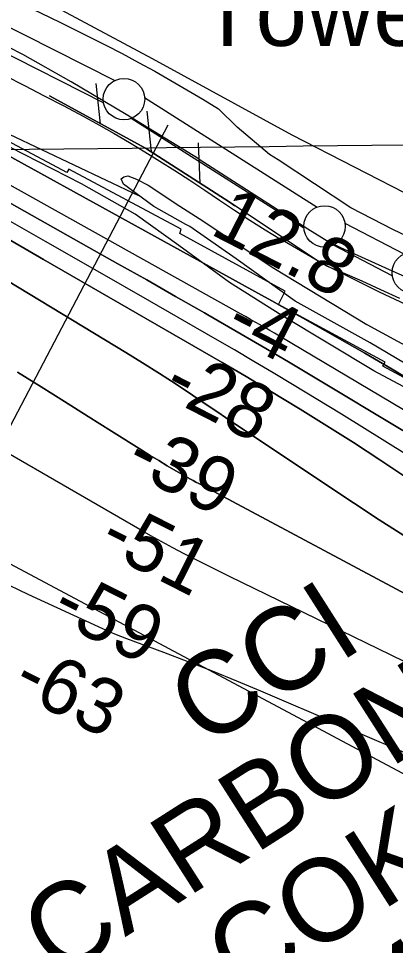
# Model space of a CAD drawing. Extents: x 3704301 to 3742427, y 506229 to 532009.
# Drawn here: x 3708455 to 3708909, y 522807 to 523925 of the extents above; entities that cross this region are included whole.
import ezdxf

# ---------------------------------------------------------------- set-up
doc = ezdxf.new("R2010")
doc.units = 0
for name, color, linetype in [('V-CHAN-NAID', 7, 'Continuous'), ('V-DOMW-IDEN', 7, 'Continuous'), ('V-FLOD-BASE', 7, 'Continuous'), ('V-GRID-MAJR', 7, 'Continuous'), ('V-LEVE-TOET', 7, 'Continuous'), ('V-RIVR-EDGE', 7, 'Continuous'), ('V-RIVR-RANG', 7, 'Continuous'), ('V-RRAP-FSHR', 7, 'Continuous'), ('V-RRAP-RVMT', 7, 'Continuous'), ('V-SITE-OTLN', 7, 'Continuous'), ('V-SITE-VEGE', 7, 'Continuous'), ('V-SURV-LINE', 7, 'Continuous'), ('V-TOPO-DPTH', 7, 'Continuous'), ('V-TOPO-MAJR', 7, 'Continuous'), ('V-TOPO-MINR', 7, 'Continuous'), ('V-TOPO-WATR', 7, 'Continuous')]:
    doc.layers.add(name, color=color, linetype=linetype)

msp = doc.modelspace()

# ---------------------------------------------------------------- linework, layer by layer
at = {"layer": 'V-FLOD-BASE'}
for points in [[(3708672.815, 523755.58), (3708584.865, 523809.742), (3708518.5160000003, 523849.131), (3708460.504, 523881.911), (3708425.5694070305, 523899.65617279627)], [(3708672.815, 523755.58), (3708745.3340000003, 523708.9), (3708803.6350000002, 523671.651), (3708829.228, 523656.09500000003), (3708842.971, 523649.02900000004), (3708909.772, 523618.89900000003), (3708991.733, 523582.653), (3709081.7430000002, 523545.007), (3709117.2800000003, 523527.583), (3709134.8170000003, 523516.739), (3709176.5300000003, 523488.916), (3709185.0640000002, 523482.31200000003), (3709195.026, 523472.868), (3709199.7770000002, 523465.30700000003), (3709202.157, 523459.634), (3709201.235, 523449.22000000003), (3709198.421, 523437.856)]]:
    msp.add_lwpolyline(points, dxfattribs=at)
at = {"layer": 'V-GRID-MAJR'}
msp.add_spline([(3708427.129, 523767.243), (3713705.816, 523829.819), (3718984.494, 523893.163), (3724263.162, 523957.275), (3729541.821, 524022.155), (3734820.471, 524087.803), (3740099.111, 524154.218), (3740099.112, 524154.218)], degree=3, dxfattribs=at)
at = {"layer": 'V-LEVE-TOET'}
for points in [[(3708424.8581686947, 523960.0234815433), (3708449.116, 523948.271), (3708504.8030000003, 523920.989), (3708560.3710000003, 523893.47000000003), (3708580.143, 523883.126), (3708599.795, 523872.554), (3708619.325, 523861.761), (3708638.73, 523850.743), (3708658.007, 523839.503), (3708677.156, 523828.047), (3708696.1720000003, 523816.371)], [(3708426.002542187, 523862.89324485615), (3708438.497, 523856.569), (3708462.225, 523844.46400000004), (3708485.91, 523832.282), (3708509.552, 523820.02900000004), (3708533.153, 523807.7), (3708551.88, 523797.282), (3708570.486, 523786.646), (3708588.967, 523775.798), (3708607.324, 523764.737), (3708625.551, 523753.467), (3708643.645, 523741.98600000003), (3708661.608, 523730.29600000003), (3708679.434, 523718.401), (3708697.419, 523706.129), (3708715.5500000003, 523694.069), (3708733.818, 523682.221), (3708752.2260000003, 523670.586), (3708770.764, 523659.169)], [(3708757.727, 523761.462), (3708718.62, 523794.482), (3708696.1720000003, 523816.371)], [(3709197.717, 523535.347), (3709110.538, 523576.313), (3709007.728, 523622.446), (3708906.809, 523670.478), (3708855.633, 523696.858), (3708767.94, 523754.859), (3708757.727, 523761.462)], [(3708914.489, 523587.677), (3708891.795, 523598.147), (3708869.001, 523608.397), (3708846.1040000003, 523618.424), (3708826.488, 523626.788), (3708770.764, 523659.169)]]:
    msp.add_lwpolyline(points, dxfattribs=at)
at = {"layer": 'V-RIVR-EDGE'}
msp.add_lwpolyline([(3708960.1091392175, 523459.0963712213), (3708883.3687410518, 523500.1083391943), (3708772.4737643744, 523567.01880682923), (3708709.537825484, 523606.79598707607), (3708648.4147308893, 523651.37129774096), (3708595.679829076, 523689.32227385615), (3708530.9354991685, 523726.1022925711), (3708444.59735574, 523770.13962617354)], dxfattribs=at)
at = {"layer": 'V-RIVR-RANG'}
msp.add_line((3708635.0474999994, 523796.8230000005), (3708431.3601537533, 523408.158769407), dxfattribs=at)
at = {"layer": 'V-RRAP-FSHR'}
for p, q in [((3708554.023, 523798.553), (3708548.645, 523847.087)), ((3708615.437, 523764.962), (3708610.059, 523813.496)), ((3708673.975, 523726.537), (3708672.1, 523775.331))]:
    msp.add_line(p, q, dxfattribs=at)
for points in [[(3709177.028, 523451.364), (3709162.396, 523470.18700000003), (3709116.876, 523494.681), (3708985.221, 523550.533), (3708890.261, 523595.17100000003), (3708817.731, 523631.577), (3708708.875, 523704.04600000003), (3708608.241, 523768.898), (3708492.609, 523832.14400000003)], [(3708492.609, 523832.14400000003), (3708608.241, 523768.898), (3708691.882, 523714.99700000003)], [(3708492.609, 523832.14400000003), (3708608.241, 523768.898), (3708708.875, 523704.04600000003), (3708715.738, 523699.477)], [(3708426.801692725, 523795.0642698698), (3708443.9034086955, 523785.80477121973), (3708599.73163284, 523711.96617915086)]]:
    msp.add_lwpolyline(points, dxfattribs=at)
at = {"layer": 'V-RRAP-RVMT'}
for p, q in [((3708513.4930000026, 523739.83000000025), (3708426.9114247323, 523785.75061843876)), ((3708515.6950000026, 523743.77500000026), (3708513.4930000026, 523739.83000000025)), ((3708651.121000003, 523671.32000000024), (3708515.6950000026, 523743.77500000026)), ((3708649.3660000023, 523665.9040000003), (3708651.121000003, 523671.32000000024)), ((3708776.3230000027, 523596.24900000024), (3708649.3660000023, 523665.9040000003)), ((3708768.3070000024, 523580.1640000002), (3708776.3230000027, 523596.24900000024)), ((3708896.733000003, 523510.96200000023), (3708768.3070000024, 523580.1640000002)), ((3708894.0200000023, 523506.0550000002), (3708896.733000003, 523510.96200000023)), ((3709020.351000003, 523437.5880000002), (3708894.0200000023, 523506.0550000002)), ((3708432.9415698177, 523273.9339576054), (3708943.5830000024, 523000.8630000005))]:
    msp.add_line(p, q, dxfattribs=at)
at = {"layer": 'V-SITE-OTLN'}
for p, q in [((3708616.5130000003, 523876.8449999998), (3708424.6245523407, 523979.85198328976)), ((3708784.713, 523784.711), (3708616.5130000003, 523876.84500000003)), ((3708968.245, 523690.2549999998), (3708784.713, 523784.7109999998))]:
    msp.add_line(p, q, dxfattribs=at)
at = {"layer": 'V-SITE-VEGE'}
msp.add_lwpolyline([(3708952.688, 523490.254), (3708878.845, 523534.081), (3708788.3340000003, 523584.41500000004), (3708717.449, 523635.385), (3708661.4560000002, 523674.5), (3708656.691, 523676.868), (3708617.988, 523698.777), (3708581.65, 523725.45), (3708578.66, 523731.985), (3708582.221, 523734.371), (3708586.977, 523735.571), (3708597.096, 523731.43700000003), (3708611.3850000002, 523724.332), (3708649.506, 523698.853), (3708672.733, 523684.042), (3708762.671, 523624.195), (3708874.631, 523556.077), (3709045.524, 523463.12200000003)], dxfattribs=at)
at = {"layer": 'V-SURV-LINE'}
for points in [[(3708425.2807335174, 523924.1577248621), (3708571.080569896, 523850.54480518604)], [(3708557.5410878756, 523823.77387222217), (3708425.6790540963, 523890.34973089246)], [(3708607.068558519, 523830.09161094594), (3708815.0232567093, 523697.95805869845)], [(3708798.9325323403, 523672.63833132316), (3708590.977370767, 523804.77217800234)], [(3708848.5130716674, 523678.5779782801), (3708919.4626374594, 523641.35594190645)], [(3708905.530769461, 523614.7871050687), (3708834.5813502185, 523652.00906455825)]]:
    msp.add_lwpolyline(points, dxfattribs=at)
for centre in [(3708582.15328, 523828.1511700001), (3708823.84779, 523674.57925), (3708930.19607, 523618.78569000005)]:
    msp.add_circle(centre, 25, dxfattribs=at)
at = {"layer": 'V-TOPO-DPTH'}
for points in [[(3708427.113091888, 523768.63384779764), (3708747.93709737, 523591.52124611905), (3708760.2676043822, 523584.6984678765), (3708772.589227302, 523577.85971946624), (3708784.8975240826, 523570.99701580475), (3708797.196936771, 523564.11834197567), (3708839.2242122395, 523540.56012094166), (3708872.3657300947, 523521.6146522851), (3708905.2875659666, 523502.30181555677), (3708937.879878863, 523482.4379267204)], [(3708427.7791281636, 523712.1031246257), (3708539.907099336, 523649.22717102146), (3708574.7640026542, 523629.61773803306), (3708609.5845683, 523609.9441973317), (3708644.3506274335, 523590.1744950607), (3708679.0803488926, 523570.34068507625), (3708683.351154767, 523567.8938360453), (3708715.854107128, 523549.1263235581), (3708748.271585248, 523530.2134325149), (3708780.5608520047, 523511.0824736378), (3708812.7646445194, 523491.806136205), (3708918.0096827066, 523428.326495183)], [(3708918.0096827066, 523428.326495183), (3708812.7646445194, 523491.806136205), (3708780.5608520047, 523511.0824736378), (3708748.271585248, 523530.2134325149), (3708715.854107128, 523549.1263235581), (3708683.351154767, 523567.8938360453), (3708679.0803488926, 523570.34068507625), (3708644.3506274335, 523590.1744950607), (3708609.5845683, 523609.9441973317), (3708574.7640026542, 523629.61773803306), (3708539.907099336, 523649.22717102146), (3708427.7791281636, 523712.1031246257)], [(3708921.8144990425, 523371.8449279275), (3708890.303524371, 523392.93843949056), (3708858.5871277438, 523413.71314405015), (3708826.5625981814, 523434.00963810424), (3708794.3326466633, 523453.987325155), (3708758.0921977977, 523476.0762695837), (3708743.7985313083, 523484.7200691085), (3708729.465145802, 523493.2969622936), (3708715.072181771, 523501.77349597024), (3708700.639498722, 523510.18312330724), (3708485.4053483, 523634.59041137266), (3708428.305013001, 523667.4679429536)], [(3708428.305013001, 523667.4679429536), (3708485.4053483, 523634.59041137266), (3708700.639498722, 523510.18312330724), (3708715.072181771, 523501.77349597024), (3708729.465145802, 523493.2969622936), (3708743.7985313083, 523484.7200691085), (3708758.0921977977, 523476.0762695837), (3708794.3326466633, 523453.987325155), (3708826.5625981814, 523434.00963810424), (3708858.5871277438, 523413.71314405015), (3708890.303524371, 523392.93843949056), (3708921.8144990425, 523371.8449279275)], [(3708952.452662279, 523280.75897873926), (3708889.8327228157, 523320.62092029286), (3708827.753952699, 523361.3527432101), (3708722.65631127, 523431.8777602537), (3708713.536591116, 523438.0059914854), (3708704.422136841, 523444.1420337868), (3708695.315581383, 523450.2897926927), (3708686.214291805, 523456.4453626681), (3708664.828447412, 523470.92952448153), (3708644.939076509, 523484.1783067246), (3708624.9176331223, 523497.2208991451), (3708604.6980810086, 523509.9542068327), (3708584.3464564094, 523522.4813246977), (3708428.9052626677, 523616.5209465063)], [(3708428.9052626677, 523616.5209465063), (3708584.3464564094, 523522.4813246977), (3708604.6980810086, 523509.9542068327), (3708624.9176331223, 523497.2208991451), (3708644.939076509, 523484.1783067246), (3708664.828447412, 523470.92952448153), (3708686.214291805, 523456.4453626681), (3708695.315581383, 523450.2897926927), (3708704.422136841, 523444.1420337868), (3708713.536591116, 523438.0059914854), (3708722.65631127, 523431.8777602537), (3708827.753952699, 523361.3527432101), (3708889.8327228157, 523320.62092029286), (3708952.452662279, 523280.75897873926)], [(3709125.493004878, 523121.7417145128), (3708672.2480643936, 523364.16437444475), (3708668.8773070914, 523365.988932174), (3708665.5189389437, 523367.8357553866), (3708662.179154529, 523369.7159768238), (3708658.8517592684, 523371.6184637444), (3708644.7243759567, 523379.78974272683), (3708634.3774296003, 523385.85229540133), (3708624.076931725, 523391.9917899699), (3708613.8461065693, 523398.2466973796), (3708603.661729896, 523404.5785466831), (3708567.2753733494, 523427.4853477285), (3708538.9320787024, 523445.32738940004), (3708510.5880023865, 523463.16818912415), (3708482.242753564, 523481.0071259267), (3708453.896723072, 523498.8448207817)], [(3708453.896723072, 523498.8448207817), (3708482.242753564, 523481.0071259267), (3708510.5880023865, 523463.16818912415), (3708538.9320787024, 523445.32738940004), (3708567.2753733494, 523427.4853477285), (3708603.661729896, 523404.5785466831), (3708613.8461065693, 523398.2466973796), (3708624.076931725, 523391.9917899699), (3708634.3774296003, 523385.85229540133), (3708644.7243759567, 523379.78974272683), (3708658.8517592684, 523371.6184637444), (3708662.179154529, 523369.7159768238), (3708665.5189389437, 523367.8357553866), (3708668.8773070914, 523365.988932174), (3708672.2480643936, 523364.16437444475), (3709125.493004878, 523121.7417145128)]]:
    msp.add_lwpolyline(points, dxfattribs=at)
at = {"layer": 'V-TOPO-MAJR'}
msp.add_lwpolyline([(3709709.5431173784, 522748.20894958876), (3709681.1022635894, 522763.44220229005), (3709652.548335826, 522778.46710977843), (3709234.962201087, 522995.26852753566), (3709223.4809313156, 523001.1742643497), (3709211.970361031, 523007.0217795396), (3709200.415839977, 523012.7819622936), (3709188.8320184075, 523018.4839234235), (3708709.327672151, 523252.2613668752), (3708695.636786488, 523258.98924790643), (3708681.9743451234, 523265.7739610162), (3708668.354570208, 523272.6439222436), (3708654.763239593, 523279.5707155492), (3708641.248391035, 523286.6411769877), (3708627.807032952, 523293.8462877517), (3708614.4759105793, 523301.2533725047), (3708601.2182786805, 523308.7951065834), (3708431.3724275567, 523407.117013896)], dxfattribs=at)
at = {"layer": 'V-TOPO-MINR'}
for points in [[(3709068.5479360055, 523364.2251498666), (3708769.5124735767, 523542.1923348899), (3708763.708538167, 523545.6247803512), (3708757.892088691, 523549.0357507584), (3708752.0568681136, 523552.41450858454), (3708746.2091334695, 523555.77179135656), (3708740.347881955, 523559.1056552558), (3708734.4811229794, 523562.42977070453), (3708728.6061028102, 523565.7392634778), (3708722.7255751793, 523569.03900780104), (3708427.518720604, 523734.2055658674)], [(3708918.0096827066, 523428.326495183), (3708812.7646445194, 523491.806136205), (3708780.5608520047, 523511.0824736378), (3708748.271585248, 523530.2134325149), (3708715.854107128, 523549.1263235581), (3708683.351154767, 523567.8938360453), (3708679.0803488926, 523570.34068507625), (3708644.3506274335, 523590.1744950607), (3708609.5845683, 523609.9441973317), (3708574.7640026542, 523629.61773803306), (3708539.907099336, 523649.22717102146), (3708427.7791281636, 523712.1031246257)], [(3708948.836652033, 523382.66203473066), (3708896.7031576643, 523415.5023283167), (3708844.287186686, 523447.9004811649), (3708785.3610367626, 523483.8044501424), (3708762.144296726, 523497.8312478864), (3708738.858357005, 523511.7412078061), (3708715.4686177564, 523525.4759109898), (3708692.0096788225, 523539.0937763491), (3708613.372454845, 523584.34860899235), (3708550.488250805, 523620.40998974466), (3708487.5310529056, 523656.3430251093), (3708428.0388623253, 523690.05783890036)], [(3708921.8144990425, 523371.8449279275), (3708890.303524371, 523392.93843949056), (3708858.5871277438, 523413.71314405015), (3708826.5625981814, 523434.00963810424), (3708794.3326466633, 523453.987325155), (3708758.0921977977, 523476.0762695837), (3708743.7985313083, 523484.7200691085), (3708729.465145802, 523493.2969622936), (3708715.072181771, 523501.77349597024), (3708700.639498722, 523510.18312330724), (3708485.4053483, 523634.59041137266), (3708428.305013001, 523667.4679429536)], [(3708952.452662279, 523280.75897873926), (3708889.8327228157, 523320.62092029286), (3708827.753952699, 523361.3527432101), (3708722.65631127, 523431.8777602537), (3708713.536591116, 523438.0059914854), (3708704.422136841, 523444.1420337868), (3708695.315581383, 523450.2897926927), (3708686.214291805, 523456.4453626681), (3708664.828447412, 523470.92952448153), (3708644.939076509, 523484.1783067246), (3708624.9176331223, 523497.2208991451), (3708604.6980810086, 523509.9542068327), (3708584.3464564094, 523522.4813246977), (3708428.9052626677, 523616.5209465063)], [(3709125.493004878, 523121.7417145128), (3708672.2480643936, 523364.16437444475), (3708668.8773070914, 523365.988932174), (3708665.5189389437, 523367.8357553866), (3708662.179154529, 523369.7159768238), (3708658.8517592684, 523371.6184637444), (3708644.7243759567, 523379.78974272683), (3708634.3774296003, 523385.85229540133), (3708624.076931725, 523391.9917899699), (3708613.8461065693, 523398.2466973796), (3708603.661729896, 523404.5785466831), (3708567.2753733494, 523427.4853477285), (3708538.9320787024, 523445.32738940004), (3708510.5880023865, 523463.16818912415), (3708482.242753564, 523481.0071259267), (3708453.896723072, 523498.8448207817)], [(3709725.979140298, 522628.7922709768), (3709707.83480855, 522639.16174446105), (3709689.5977664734, 522649.367284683), (3709671.298917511, 522659.46353606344), (3709210.4827111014, 522911.01349879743), (3709192.54777705, 522920.4741295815), (3709174.4444116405, 522929.5879631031), (3709156.088399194, 522938.1816007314), (3709137.5639553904, 522946.42844109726), (3708747.047314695, 523113.6453905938), (3708717.9957611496, 523125.83717387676), (3708688.8313845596, 523137.74686392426), (3708659.4977734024, 523149.23341411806), (3708630.0513391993, 523160.43787107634), (3708585.723251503, 523176.93875455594), (3708578.3910174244, 523179.7646692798), (3708571.105145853, 523182.70187666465), (3708563.8888180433, 523185.8060230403), (3708556.7188527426, 523189.0214620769), (3708466.784220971, 523230.6036722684), (3708433.264697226, 523246.5080849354)]]:
    msp.add_lwpolyline(points, dxfattribs=at)
at = {"layer": 'V-TOPO-WATR'}
msp.add_lwpolyline([(3708937.879878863, 523482.4379267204), (3708905.2875659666, 523502.30181555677), (3708872.3657300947, 523521.6146522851), (3708839.2242122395, 523540.56012094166), (3708797.196936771, 523564.11834197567), (3708784.8975240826, 523570.99701580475), (3708772.589227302, 523577.85971946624), (3708760.2676043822, 523584.6984678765), (3708747.93709737, 523591.52124611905), (3708427.113091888, 523768.63384779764)], dxfattribs=at)

# ---------------------------------------------------------------- texts
at = {"layer": 'V-CHAN-NAID'}
for s, p in [('CCI', (3708679.0165192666, 523043.7700792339)), ('CARBON', (3708501.9745251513, 522764.73652563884)), ('COKE', (3708723.8973958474, 522740.265195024)), ('(89.1) (4)', (3708557.369849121, 522467.9404555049))]:
    msp.add_text(s, height=100.00000199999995, rotation=32.54018620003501, dxfattribs=at).set_placement(p)
at = {"layer": 'V-DOMW-IDEN'}
msp.add_text('Towers', height=82.999832, dxfattribs=at).set_placement((3708672.9983566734, 523892.4496280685))
at = {"layer": 'V-RIVR-RANG'}
for s, rotation, p in [('12.8', 332.84832571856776, (3708684.3222059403, 523666.2404652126)), ('12.8', 332.84832571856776, (3708684.3222059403, 523666.2404652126)), ('-4', 332.84832571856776, (3708700.8660271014, 523545.3714249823)), ('-4', 332.84832571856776, (3708700.8660271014, 523545.3714249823)), ('-28', 332.84832571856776, (3708626.1070966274, 523471.32831903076)), ('-39', 333.1282777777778, (3708580.8861747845, 523381.68764500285)), ('-51', 333.1282777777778, (3708549.113389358, 523285.6824848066)), ('-59', 333.1282777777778, (3708491.4589556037, 523202.7922836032)), ('-63', 333.1282777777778, (3708444.8624715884, 523114.298418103))]:
    msp.add_text(s, height=66.99999999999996, rotation=rotation, dxfattribs=at).set_placement(p)

doc.saveas('drawing.dxf')
